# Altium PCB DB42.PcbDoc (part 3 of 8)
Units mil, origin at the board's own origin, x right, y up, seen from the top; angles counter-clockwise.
Board outline 3236.22 x 4456.69 mil, 8 copper layers (Top Layer, MidLayer1, MidLayer2, GND-Layer5, MidLayer3, VCC, MidLayer4, Bottom Layer), stack 62.194 mil thick; 214 components, 470 nets, 1802 pads, 1663 vias.
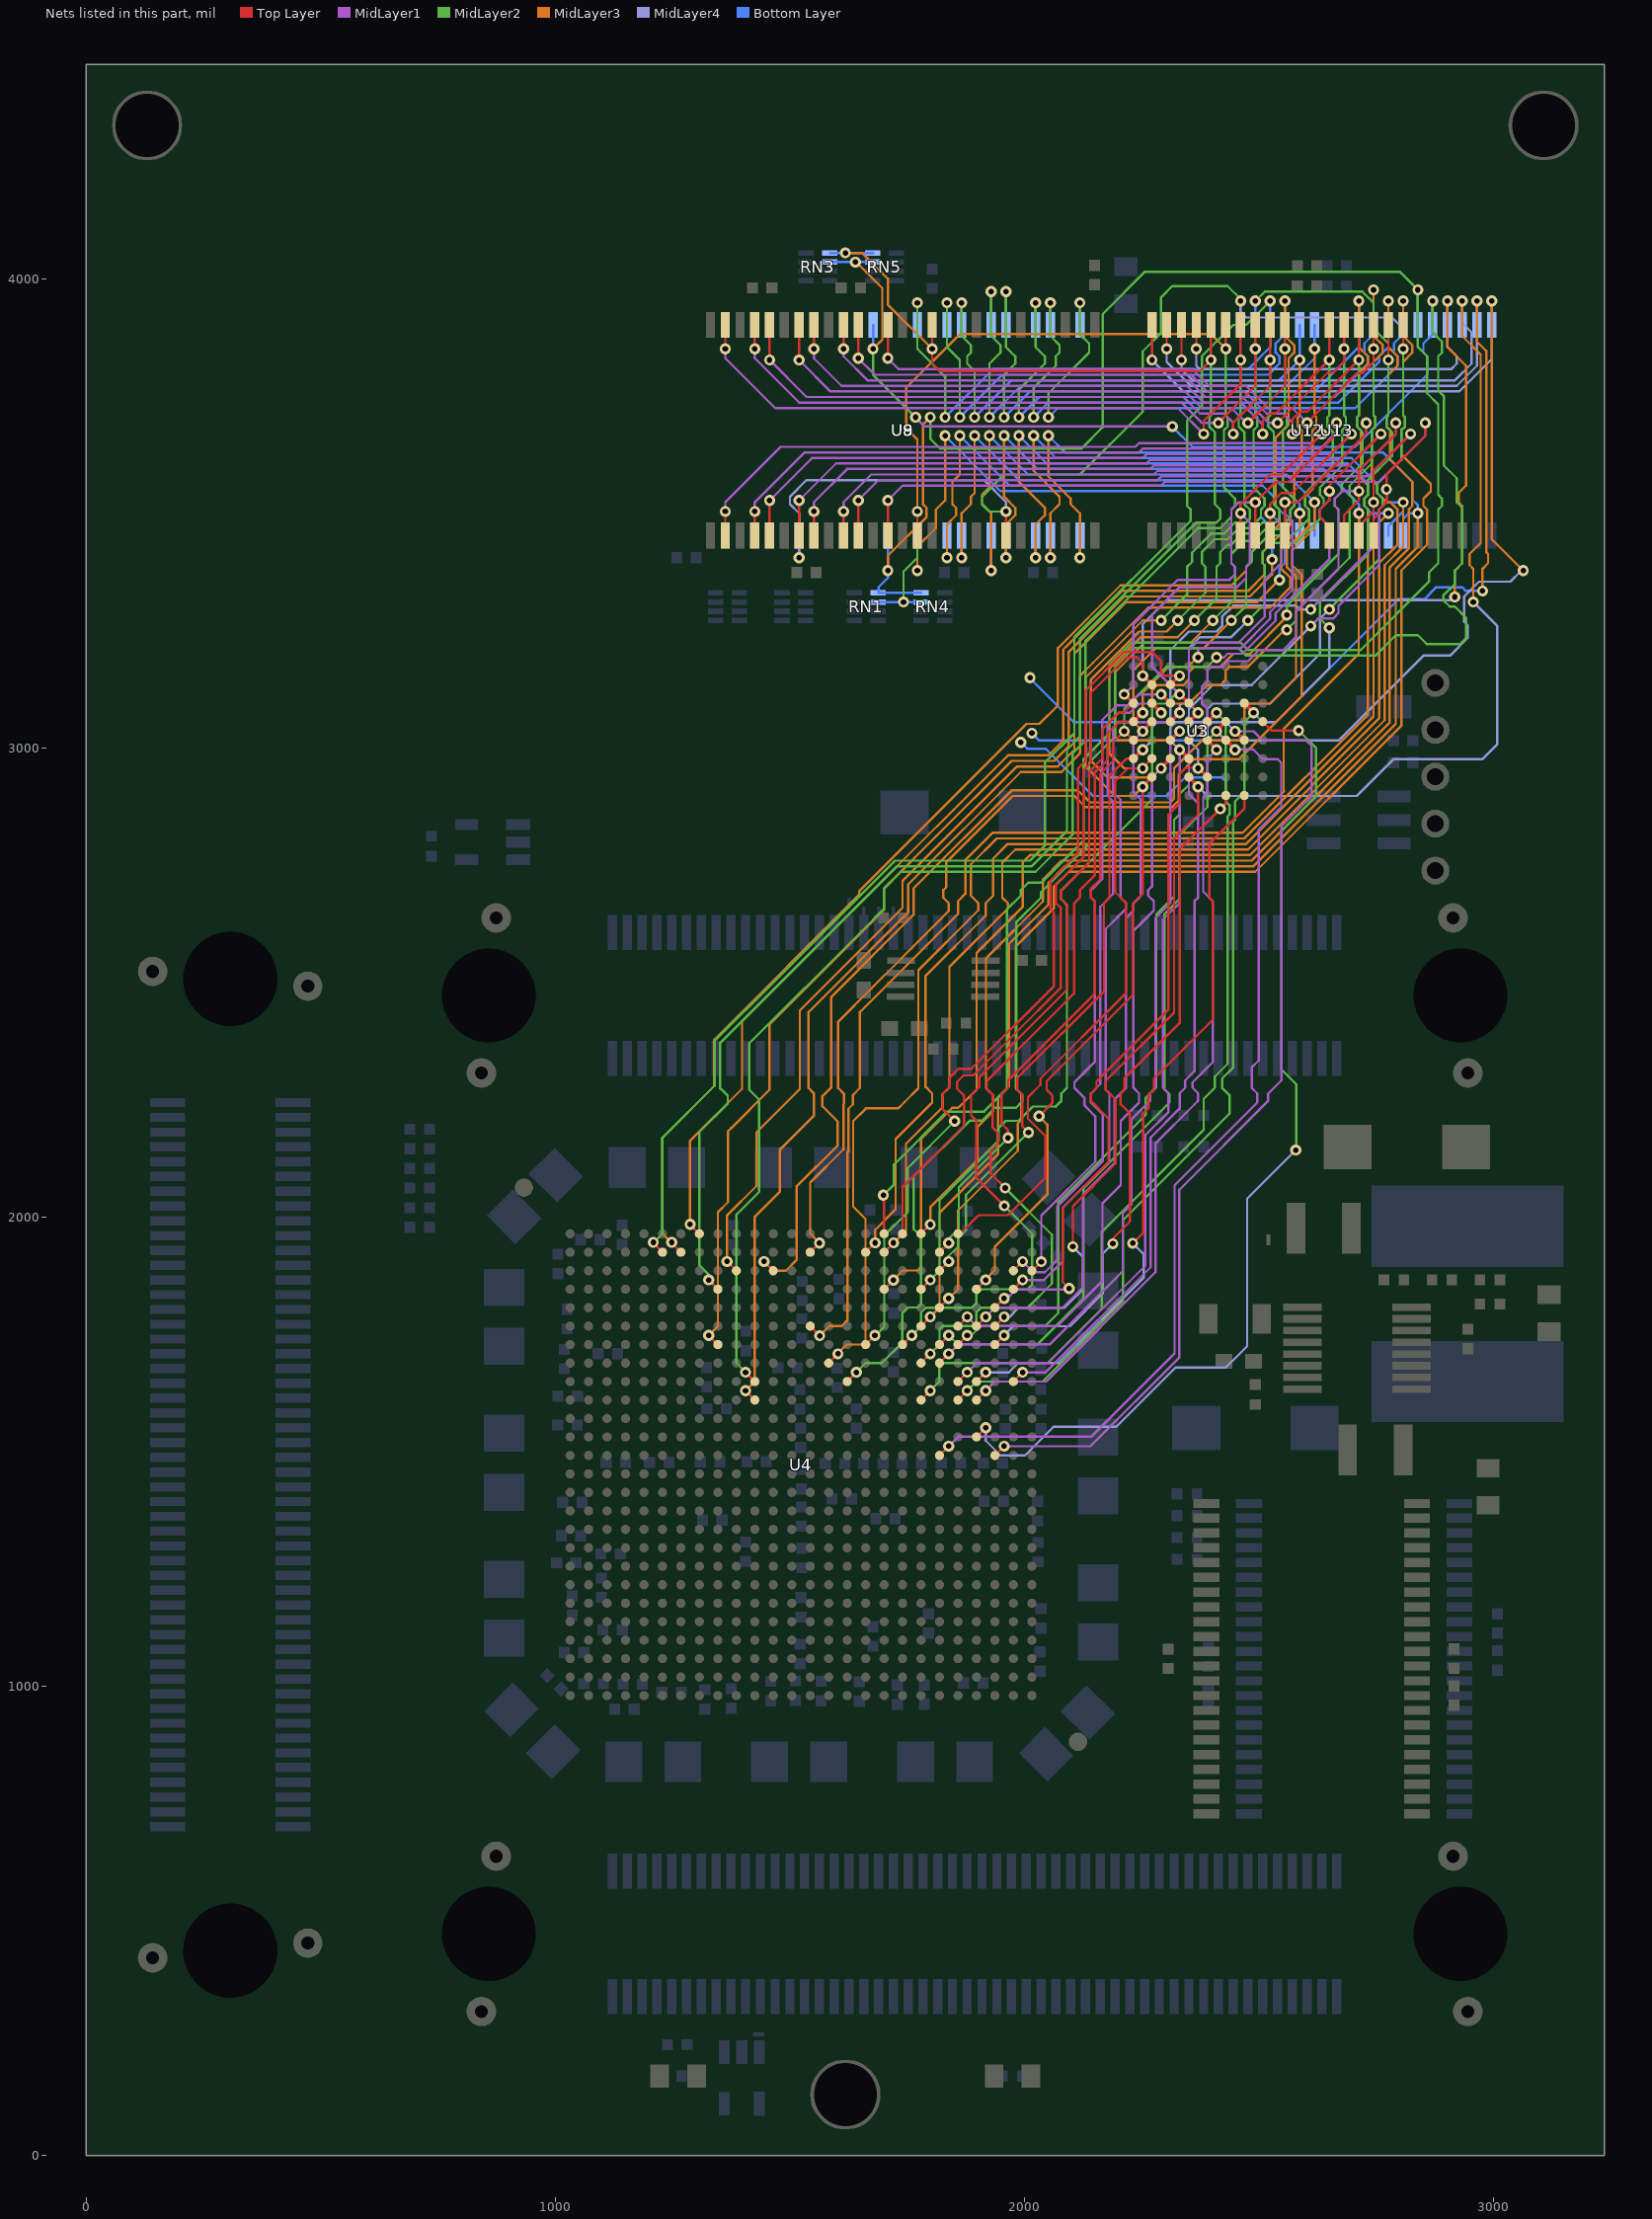
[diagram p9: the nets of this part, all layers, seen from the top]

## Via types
v1: diameter 23.62, hole 11.81, Top Layer to Bottom Layer, 1081 vias
v2: diameter 23.62, hole 11.81, Top Layer to Bottom Layer, tented both sides, 466 vias
v3: diameter 27.56, hole 15.75, Top Layer to Bottom Layer, 116 vias

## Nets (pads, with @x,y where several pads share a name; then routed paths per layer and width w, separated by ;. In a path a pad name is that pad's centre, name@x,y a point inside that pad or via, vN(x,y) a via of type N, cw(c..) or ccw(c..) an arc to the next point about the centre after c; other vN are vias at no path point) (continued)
BUS_A16: U3.D7 U4.E24 U8.21 U9.21 U12.27 U13.27 | length 4892.7
  Top Layer w5: U4.E24@1937.01,1807.09 v1(1956.69,1826.77) ; U8.21@1960.63,3452.76 v2(1960.63,3503.93) ; v1(2095,1848) 2081.5,1861.5 2081.5,2019.5 2179,2117.01 2179,2209.77 2141.73,2247.03 2141.73,2263.78 2153.54,2275.59 2153.54,2289.37 2307.09,2442.91 2307.09,2858.27 2330.71,2881.89 2330.71,2944.88 2343.51,2957.68 v1@2370.08,2957.68 ; v2(2807.09,3850.39) U12.27@2807.09,3901.57
  Top Layer w7.87: v1@2370.57,2957.19 U3.D7@2389.76,2937.99
  MidLayer1 w5: v1(1956.69,1826.77) 1963.11,1833.19 1969.97,1833.19 1982.86,1846.08 2092.88,1846.08 v1@2092.98,1845.98
  MidLayer2 w5: v2(1960.63,3503.93) 1925.2,3503.93 1909.45,3519.68 1909.45,3535.43 1925.2,3551.18 1956.69,3582.68 2118.11,3582.68 2251.97,3716.54 2251.97,3845.28 2291.34,3884.64 2291.34,3960.63 2314.96,3984.25 2433.07,3984.25 2460.63,3956.69 v2(2460.63,3952.76) ; v1(2649.61,3295.28) 2755.91,3401.57 2755.91,3507.87 2763.78,3515.75 2763.78,3531.5 2751.97,3543.31 2751.97,3562.99 2803.15,3614.17 2803.15,3677.17 2811.02,3685.04 2811.02,3704.72 2807.09,3708.66 v2(2807.09,3850.39)
  MidLayer4 w5: v2(1519.68,3405.51) 1519.68,3500 1500,3519.68 1500,3535.43 1535.43,3570.87 1913.38,3570.87 1960.63,3523.63 v2(1960.63,3503.93) ; v1(2370.08,2956.69) 2370.08,2996.06 2350.39,3015.75 2350.39,3043.31 2362.2,3055.12 2377.95,3055.12 2389.76,3066.93 2389.76,3082.68 2401.57,3094.49 2523.62,3094.49 2629.92,3200.79 2629.92,3275.59 v1(2649.61,3295.28) ; v2(2460.63,3952.76) 2460.63,3929.13 2472.44,3917.32 2783.46,3917.32 2807.09,3893.7 v2(2807.09,3850.39)
  Bottom Layer w5: v2(1519.68,3405.51) U9.21@1519.69,3452.76 ; U13.27@2460.63,3901.57 v2(2460.63,3952.76)
BUS_A17: U3.E7 U4.F24 U12.42 U13.42 | length 4073.9
  Top Layer w5: U4.F24@1937.01,1767.72 v1(1956.69,1787.4) ; v1(2103.15,1937.01) 2103.15,2023.32 2194,2114.17 2194,2250.88 2179.92,2264.97 2172.82,2272.06 2172.82,2289.76 2318.9,2435.84 2318.9,2807.09 2370.08,2858.27 v1(2370.08,2917.32) ; v2(2334.64,3826.77) U12.42@2334.64,3901.57
  Top Layer w7.87: U3.E7@2350.39,2937.99 v1(2370.08,2917.32)
  MidLayer3 w5: v2(2933.07,3952.76) 2933.07,3877.95 2972.44,3838.58 2972.44,3437.01 2948.82,3413.39 2948.82,3389.76 2956.69,3381.89 v1(2956.69,3311.02)
  MidLayer4 w5: v1(1956.69,1787.4) 1968.5,1787.4 1987.98,1806.88 2085.23,1806.88 2124.41,1846.06 2124.41,1915.75 v1(2103.15,1937.01) ; v2(2334.64,3826.77) 2334.64,3807.09 2358.27,3783.46 2917.32,3783.46 2952.76,3818.9 2952.76,3885.83 2933.07,3905.51 v2(2933.07,3952.76) ; v1(2370.08,2917.32) 2389.76,2897.64 2708.27,2897.64 2787.01,2976.38 2976.38,2976.38 3007.87,3007.87 3007.87,3259.84 v1(2956.69,3311.02)
  Bottom Layer w5: U13.42@2933.07,3901.57 v2(2933.07,3952.76)
BUS_A18: U3.B3 U4.K22 U12.43 U13.43 | length 4068.5
  Top Layer w5: U4.K22@1858.27,1610.24 v1(1877.95,1629.92) ; v2(2303.15,3850.39) U12.43@2303.15,3901.57
  Top Layer w7.87: U3.B3@2468.5,3095.47 v1@2488.19,3075.79
  MidLayer2 w5: v1(1877.95,1629.92) 1897.64,1649.61 2038.29,1649.61 2210.06,1821.38 2210.06,1993.58 2437.01,2220.53 2437.01,2259.84 2421.26,2275.59 2421.26,2295.28 2444.88,2318.9 2444.88,2673.23 2444.88,2842.52 2448.82,2846.46 2448.82,2885.83 2468.5,2905.51 2468.5,2976.38 2468.5,3055.12 v1(2488.19,3074.8)
  MidLayer3 w5: v2(2964.57,3952.76) 2964.57,3866.14 2984.25,3846.46 2984.25,3417.32 2988.19,3413.39 2988.19,3393.7 2976.38,3381.89 v1(2976.38,3334.65)
  MidLayer4 w5: v2(2303.15,3850.39) 2303.15,3822.83 2354.33,3771.65 2921.26,3771.65 2964.57,3814.96 v2(2964.57,3952.76)
  Bottom Layer w5: v1(2488.19,3074.8) 2507.87,3055.12 2535.43,3055.12 2796.99,3316.68 2852.11,3316.68 2877.95,3342.52 2933.07,3342.52 2940.94,3334.65 v1(2976.38,3334.65) ; U13.43@2964.57,3901.57 v2(2964.57,3952.76)
BUS_A19: U3.C4 U4.G21 U12.44 U13.44 | length 4235
  Top Layer w5: U4.G21@1818.9,1728.35 v1(1838.58,1748.03) ; v2(2271.65,3826.77) U12.44@2271.65,3901.57
  Top Layer w7.87: v1(2409.45,3035.43) U3.C4@2429.13,3056.1
  MidLayer2 w5: v1(1838.58,1748.03) 1858.27,1728.35 2027.48,1728.35 2125.44,1826.3 2125.44,2060.5 2309.45,2244.5 2309.45,2261.23 2298.62,2272.06 2298.62,2645.98 2330.71,2678.06 2330.71,2814.96 2389.76,2874.02 2389.76,3015.75 v1(2409.45,3035.43)
  MidLayer3 w5: v2(2996.06,3952.76) 2996.06,3633.86 2996.06,3444.88 v1(3062.99,3377.95)
  MidLayer4 w5: v2(2271.65,3826.77) 2338.58,3759.84 2926.67,3759.84 2996.06,3829.23 v2(2996.06,3952.76) ; v1(2409.45,3035.43) 2429.13,3015.75 2669.29,3015.75 2850.39,3196.85 2906.85,3196.85 2944.88,3234.88 2944.88,3260.83 2937.01,3268.7 2937.01,3322.83 2968.5,3354.33 3035.43,3354.33 3059.06,3377.95 v1(3062.99,3377.95)
  Bottom Layer w5: U13.44@2996.06,3901.57 v2(2996.06,3952.76)
BUS_A20: U3.D5 U4.K23 U12.28 U13.28 | length 3357.9
  Top Layer w5: U4.K23@1897.64,1610.24 v1(1917.32,1629.92) ; v2(2775.59,3826.77) U12.28@2775.59,3901.57
  Top Layer w7.87: U3.D5@2389.76,3016.73 v1(2409.45,2996.06)
  MidLayer1 w5: v1(1917.32,1629.92) 1937.01,1649.61 2046.16,1649.61 2279.03,1882.48 2279.03,2156.98 2362.44,2240.4 2370.08,2248.03 2370.08,2263.78 2358.27,2275.59 2358.27,2287.4 2401.57,2330.71 2401.57,2673.23 2380.91,2693.9 2380.91,2894.69 2389.76,2903.54 2389.76,2976.38 v1(2409.45,2996.06)
  MidLayer2 w5: v2(2492.13,3952.76) 2511.81,3972.44 2720.47,3972.44 2744.09,3948.82 2744.09,3893.7 2775.59,3862.21 v2(2775.59,3826.77) 2775.59,3708.66 2771.65,3704.72 2771.65,3685.04 2783.46,3673.23 2783.46,3622.05 2732.28,3570.87 2732.28,3539.37 2724.41,3531.5 2724.41,3515.75 2732.28,3507.87 2732.28,3413.39 2629.92,3311.02 2629.92,3275.59 v1(2649.61,3255.91)
  MidLayer4 w5: v1(2409.45,2996.06) 2389.76,3015.75 2389.76,3043.31 2401.57,3055.12 2535.43,3055.12 2649.61,3169.29 v1(2649.61,3255.91)
  Bottom Layer w5: U13.28@2492.13,3901.57 v2(2492.13,3952.76)
BUS_A21: U3.D4 U4.K20 | length 1904.6
  Top Layer w5: U4.K20@1779.53,1610.24 v1(1799.21,1629.92)
  Top Layer w7.87: U3.D4@2389.76,3056.1 v1(2409.45,3074.8)
  MidLayer2 w5: v1(1799.21,1629.92) 1818.52,1649.23 1818.52,1678.76 1828.74,1688.98 2049.21,1688.98 2164.65,1804.41 2164.65,1968.7 2381.89,2185.95 2381.89,2251.97 2405.51,2275.59 2405.51,2299.21 2433.07,2326.77 2433.07,2749.01 2433.07,2854.33 2437.01,2858.27 2437.01,2877.95 2429.13,2885.83 2429.13,2909.45 2429.13,3055.12 v1(2409.45,3074.8)
BUS_A22: U3.C5 U4.N21 | length 2538.3
  Top Layer w5: U4.N21@1818.9,1492.13 v1(1838.58,1511.81)
  Top Layer w7.87: U3.C5@2429.13,3016.73 v1@2448.82,2997.05
  MidLayer1 w5: v1(1838.58,1511.81) 1858.64,1531.87 2142.08,1531.87 2319.88,1709.67 2319.88,2067.91 2496.06,2244.09 2496.06,2263.78 2484.25,2275.59 2484.25,2318.9 2499.36,2334.01 2499.36,2826.05 2547.24,2873.93 2547.24,2968.5 2539.37,2976.38 2507.87,2976.38 2487.2,2997.05 v1@2448.82,2997.05
  Bottom Layer w5: v1(2015.75,3031.5) 2031.5,3015.75 2429.13,3015.75 v1@2447.83,2997.05
  other v1: 2448.82,2996.06
BUS_A23: U3.B8 U4.J23 | length 1604.7
  Top Layer w5: U4.J23@1897.64,1649.61 v1(1917.32,1669.29) ; v1(2230.73,1944.38) 2253.36,1967.02 2253.36,2221.36 2255,2223 ; 2254.75,2223.25 2264.96,2233.46 2264.96,2261.02 2275.59,2271.65 2275.59,2295.27 2401.57,2421.26 2401.57,2673.23 2393.7,2681.1 2393.7,2731.56 ; 2393.7,2716.54 2393.7,2795.28 2468.51,2870.08 U3.B8@2468.5,2898.62
  MidLayer4 w5: v1@1918.3,1669.29 1966.93,1669.29 1986.72,1689.08 2072.15,1689.08 2254.44,1871.37 2254.44,1920.67 v1(2230.73,1944.38)
BUS_A24: U3.C8 U4.G24 | length 2027.6
  Top Layer w5: U4.G24@1937.01,1728.35 v1(1956.69,1748.03) ; v1@2189.4,1944.38 2189.4,1955.21 2224.82,1990.63 2224.82,2220.74 2205,2240.57 2205,2264.05 2212.8,2271.85 2212.8,2295.47 2330.71,2413.39 2330.71,2783.46 2429.14,2881.89 U3.C8@2429.13,2898.62
  MidLayer4 w5: v1(1956.69,1748.03) 1956.69,1748.27 1975.91,1767.48 2096.62,1767.48 2166.54,1837.4 2166.54,1921.52 v1(2188.42,1943.4)
  Bottom Layer w5: v1(1992.13,3011.81) 2006.09,2998.31 2045.43,2998.31 2146.1,2897.64 2303.15,2897.64 2342.52,2937.01 2421.26,2937.01 2429.13,2929.13 2429.13,2881.89 v1(2417.32,2870.08)
BUS_D0: U3.E3 U4.D20 U8.2 U12.7 | length 3891.2
  Top Layer w5: U8.2@1362.21,3452.76 v2(1362.2,3503.93) ; U4.D20@1779.53,1846.46 v1(1799.21,1866.14) ; U12.7@2460.63,3452.76 v1(2460.63,3500) 2460.63,3519.69 2523.62,3582.68 2547.24,3582.68 v2(2633.86,3669.29)
  Top Layer w7.87: v1(2330.71,3114.17) U3.E3@2350.4,3095.48
  MidLayer1 w5: v2(1362.2,3503.93) 1362.2,3523.62 1480.31,3641.73 2236.22,3641.73 2244.09,3649.61 2614.17,3649.61 v2(2633.86,3669.29) ; v1(2330.71,3114.17) 2271.65,3173.23 2271.65,3283.46 2330.71,3342.52 2452.76,3342.52 2472.44,3362.2 2472.44,3385.83 2480.31,3393.7 2480.31,3480.32 v1(2460.63,3500)
  MidLayer2 w5: v1(1799.21,1866.14) 1818.9,1885.83 1818.9,2036.73 1944.38,2162.21 1944.38,2189.4 1960.13,2205.14 1987.68,2205.14 2018.18,2235.65 2066.4,2235.65 ; 2066.57,2235.47 2077.1,2246 2078.74,2247.64 2078.74,2263.78 2090.55,2275.59 2090.55,2665.35 2078.74,2677.17 2078.74,2696.85 2094.49,2712.6 ; 2084.64,2702.76 2271.65,2889.77 2271.65,3086.61 2279.53,3094.49 2302.17,3094.49 2321.85,3114.17 v1(2330.71,3114.17)
BUS_D1: U3.H3 U4.G19 U8.4 U12.8 | length 4174.9
  Top Layer w5: U8.4@1425.2,3452.76 v2(1425.19,3503.93) ; U4.G19@1740.16,1728.35 v1(1759.84,1748.03) ; v1(1957,2024) 1897,2084 1897,2206 1886.22,2216.78 1886.22,2260.24 1903.54,2277.56 1903.54,2297.64 2090.94,2485.04 2090.94,2664.96 2078.74,2677.17 2078.74,2696.85 2137.8,2755.91 2137.8,2949.54 2165.35,2977.1 2165.35,3039.37 2201.28,3075.3 2212.1,3075.3 U3.H3@2232.29,3095.48 ; U12.8@2492.13,3452.76 v1(2492.13,3523.62) 2535.43,3566.93 2562.99,3566.93 2665.35,3669.29 v2(2665.35,3692.91)
  Top Layer w7.87: v1(2212.6,3114.17) U3.H3@2232.29,3095.48
  MidLayer1 w5: v2(1425.19,3503.93) 1425.19,3523.62 1531.5,3629.92 2244.09,3629.92 2251.97,3637.8 2629.92,3637.8 2665.35,3673.23 v2(2665.35,3692.91) ; v1(2212.6,3114.17) 2232.28,3133.86 2232.28,3263.78 2326.77,3358.27 2437.01,3358.27 2448.82,3370.08 2448.82,3385.83 2440.94,3393.7 2440.94,3507.87 2456.69,3523.62 v1(2492.13,3523.62)
  MidLayer2 w5: v1(1759.84,1748.03) 1779.53,1767.72 1779.53,1796.46 1790.16,1807.09 1887.8,1807.09 1897.64,1816.93 1897.64,1835.83 1908.27,1846.46 2006.69,1846.46 2016.14,1855.91 2016.14,1964.86 v1(1957,2024)
BUS_D2: U3.E4 U4.G22 U8.5 U12.9 | length 3924.7
  Top Layer w5: U8.5@1456.69,3452.76 v2(1456.69,3527.55) ; U4.G22@1858.27,1728.35 v1(1877.95,1748.03) ; U12.9@2523.62,3452.76 v1(2523.62,3500) 2523.62,3519.69 2547.24,3543.31 2570.87,3543.31 v2(2696.85,3669.29)
  Top Layer w7.87: U3.E4@2350.39,3056.1 v1(2370.08,3074.81)
  MidLayer1 w5: v2(1456.69,3527.55) 1547.24,3618.11 2251.97,3618.11 2259.84,3625.98 2653.54,3625.98 v2(2696.85,3669.29) ; v1(2370.08,3074.81) 2350.39,3094.5 2350.39,3208.66 2366.14,3224.41 2456.69,3224.41 2511.81,3279.53 2511.81,3358.27 2547.24,3393.7 2547.24,3476.38 v1(2523.62,3500)
  MidLayer2 w5: v1(1877.95,1748.03) 1887.01,1748.03 1906.69,1767.71 2043.77,1767.71 2072.3,1796.25 2072.3,2031.96 2258.28,2217.94 2258.28,2254.34 2280.91,2276.98 2280.91,2645.38 2318.9,2683.37 2318.9,2846.46 2330.71,2858.27 2330.71,2901.57 2350.39,2921.26 2350.39,3055.12 v1(2370.08,3074.81)
BUS_D3: U3.H4 U4.H20 U8.7 U12.10 | length 4178.9
  Top Layer w5: U8.7@1519.69,3452.76 v2(1519.68,3527.56) ; U4.H20@1779.53,1688.98 v1(1799.21,1708.66) ; v1(1959,2062) 1928,2093 1928,2141 1943.4,2156.4 1943.4,2179.56 1932.32,2190.64 1932.32,2260.59 1920.08,2272.83 1920.08,2290.55 1970.67,2341.14 ; 1970.47,2341.34 2087.88,2458.75 2105.53,2476.39 2105.53,2668.52 2118.11,2681.1 2118.11,2696.85 2149.61,2728.35 2149.61,2947.21 2177.17,2974.77 2177.17,3031.5 2201.78,3056.11 U3.H4@2232.28,3056.1 ; U12.10@2555.12,3452.76 v1(2555.12,3523.62) 2582.68,3523.62 2640.75,3581.69 2728.35,3669.29 v2(2728.35,3692.91)
  Top Layer w7.87: U3.H4@2232.28,3056.1 v1@2251.47,3075.3
  MidLayer1 w5: v2(1519.68,3527.56) 1598.43,3606.3 2259.84,3606.3 2267.72,3614.17 2673.23,3614.17 2728.35,3669.29 v2(2728.35,3692.91) ; v1(2370.08,3192.91) 2370.08,3208.66 2374.02,3212.6 2460.63,3212.6 2523.62,3275.59 2523.62,3289.73 2571,3337.11 2571,3484.12 2555.12,3500 v1(2555.12,3523.62)
  MidLayer2 w5: v1(1799.21,1708.66) 1799.21,1709.06 1818.9,1728.74 1818.9,1761.02 1825.59,1767.72 1887.4,1767.72 1897.64,1777.95 1897.64,1797.24 1907.48,1807.09 2007.09,1807.09 2058.27,1858.27 2058.27,1962.73 v1(1959,2062)
  MidLayer3 w5: v1(2251.97,3074.8) 2251.97,3118.11 2255.91,3122.05 2307.09,3173.23 2348.06,3173.23 2367.75,3192.91 v1(2370.08,3192.91)
BUS_D4: U3.H5 U4.B21 U8.8 U12.13 | length 3724.4
  Top Layer w5: U8.8@1551.18,3452.76 v2(1551.18,3503.94) ; U4.B21@1818.9,1925.2 v1(1838.58,1944.88) ; v1(1965.05,2168.74) 1965.05,2185.46 1951.18,2199.33 1951.18,2262.2 1965.35,2276.38 1965.35,2291.31 2149.61,2475.56 2149.61,2673.23 2141.73,2681.1 2141.73,2700.79 2161.42,2720.47 2161.42,2944.88 2188.98,2972.44 2188.98,3011.81 v1(2212.6,3035.43) U3.H5@2232.28,3016.73 ; U12.13@2649.61,3452.76 2649.61,3472.44 2629.92,3492.13 2629.92,3507.87 2649.61,3527.56 v1(2649.61,3547.24) 2649.61,3559.06 v2(2759.84,3669.29)
  MidLayer1 w5: v2(1551.18,3503.94) 1551.18,3523.62 1622.05,3594.49 2267.72,3594.49 2275.59,3602.36 2692.91,3602.36 v2(2759.84,3669.29) ; v1(2409.45,3192.91) 2425.2,3192.91 2433.07,3200.79 2464.57,3200.79 2535.43,3271.65 2535.43,3287.4 2649.61,3401.57 2649.61,3472.44 2629.92,3492.13 2629.92,3507.87 2649.61,3527.56 v1(2649.61,3547.24)
  MidLayer2 w5: v1(1838.58,1944.88) 1838.58,1953.54 1860,1974.96 1860,2063.69 v1(1965.05,2168.74) ; v1(2212.6,3035.43) 2212.6,3082.68 2303.15,3173.23 2389.76,3173.23 v1(2409.45,3192.91)
BUS_D5: U3.E5 U4.J25 U8.10 U12.14 | length 4014.6
  Top Layer w5: U8.10@1614.17,3452.76 v2(1614.17,3503.93) ; U4.J25@1976.38,1649.61 v1(1996.06,1669.29) ; U12.14@2681.1,3452.76 2681.1,3496.06 2712.6,3527.56 v1(2712.6,3547.24) 2712.6,3590.55 2791.34,3669.29 v2(2791.34,3692.91)
  Top Layer w7.87: U3.E5@2350.39,3016.73 v1(2370.08,3035.43)
  MidLayer1 w5: v2(1614.17,3503.93) 1614.17,3523.62 1673.23,3582.68 2275.59,3582.68 2283.46,3590.55 2712.6,3590.55 2791.34,3669.29 v2(2791.34,3692.91) ; v1(1996.06,1669.29) 2045.18,1669.29 2268.98,1893.09 2268.98,2169.6 2330.71,2231.32 2330.71,2263.78 2342.52,2275.59 2342.52,2291.34 2362.2,2311.02 2362.2,2673.23 2370.08,2681.1 2370.08,2720.47 ; 2370.08,2704.72 2370.08,2720.47 ; v1(2712.6,3547.24) 2677.17,3547.24 2661.42,3531.5 2661.42,3515.75 2669.29,3507.87 2669.29,3381.89 2578.74,3291.34 2578.74,3236.22 2551.18,3208.66 2500,3208.66 2476.38,3185.04 2433.07,3185.04 2421.26,3173.23 2397.64,3173.23 2389.76,3165.35 2389.76,3141.73 2377.95,3129.92 2377.95,3094.49 2389.76,3082.68 2389.76,3055.12 v1(2370.08,3035.43) 2350.39,3015.75 2350.39,2901.57 2370.08,2881.89 2370.08,2720.47
BUS_D6: U3.H6 U4.C21 U8.11 U12.15 | length 3777.6
  Top Layer w5: U8.11@1645.67,3452.76 v2(1645.66,3527.55) ; U4.C21@1818.9,1885.83 v1(1838.58,1905.51) ; v1(2008.34,2180.54) 1995.28,2193.61 1995.28,2260.63 1984.41,2271.49 1984.41,2296.22 2169.29,2481.1 2169.29,2669.29 2181.1,2681.1 2181.1,2940.94 2217.52,2977.37 U3.H6@2232.28,2977.36 ; U12.15@2712.6,3452.76 2712.6,3472.44 2744.09,3503.94 v1(2744.09,3523.62) 2744.09,3590.55 v2(2822.83,3669.29)
  Top Layer w7.87: U3.H6@2232.28,2977.36 2251.47,2996.56 v1@2251.97,2997.05
  MidLayer1 w5: v2(1645.66,3527.55) 1688.98,3570.87 2283.46,3570.87 2291.34,3578.74 2732.28,3578.74 v2(2822.83,3669.29) ; v1(2610.24,3295.28) 2744.09,3429.13 v1(2744.09,3523.62)
  MidLayer2 w5: v1(1838.58,1905.51) 1838.58,1917.33 1858.27,1937.01 1858.27,1955.12 1865.55,1962.4 ; 1865.75,1962.21 1875.59,1972.05 1875.59,2047.79 v1(2008.34,2180.54)
  MidLayer4 w5: v1(2251.97,2996.06) 2271.65,3015.75 2271.65,3043.31 2283.46,3055.12 2303.15,3055.12 2311.02,3062.99 2311.02,3208.66 2350.39,3248.03 2409.45,3248.03 2421.26,3259.84 2421.26,3279.53 2444.88,3303.15 2578.74,3303.15 2586.61,3295.28 v1(2610.24,3295.28)
BUS_D7: U3.E6 U4.J22 U8.13 U12.16 | length 4110.9
  Top Layer w5: U8.13@1708.66,3452.76 v2(1708.66,3527.55) ; U4.J22@1858.27,1649.61 v1(1877.95,1669.29) ; U12.16@2744.09,3452.76 2744.09,3488.19 2755.91,3500 2755.91,3507.87 2771.65,3523.62 v1(2771.65,3551.18) 2771.65,3582.68 2854.33,3665.35 v2(2854.33,3692.91)
  Top Layer w7.87: v1@2330.71,2997.05 2331.2,2996.56 U3.E6@2350.39,2977.36
  MidLayer1 w5: v2(1708.66,3527.55) 1740.16,3559.06 2291.34,3559.06 2299.21,3566.93 2755.91,3566.93 2854.33,3665.35 v2(2854.33,3692.91) ; v1(1877.95,1669.29) 1897.64,1688.98 2050.1,1688.98 2257.3,1896.17 2257.3,2174.64 2307.09,2224.43 2307.09,2263.78 2295.28,2275.59 2295.27,2633.86 2330.71,2669.29 2330.71,2700.79 ; 2330.71,2681.1 v1(2330.71,2996.06) v1@2330.71,2997.05 ; v1(2610.24,3259.84) 2625.98,3275.59 2657.48,3275.59 2669.29,3287.4 2669.29,3303.15 2755.91,3389.76 2755.91,3507.87 2771.65,3523.62 v1(2771.65,3551.18)
  MidLayer4 w5: v1(2330.71,2996.06) 2311.02,3015.75 2311.02,3043.31 2322.83,3055.12 2338.58,3055.12 2350.39,3066.93 2350.39,3082.68 2401.57,3133.86 2484.25,3133.86 v1(2610.24,3259.84)
BUS_D8: U3.F3 U4.C26 U8.42 U12.29 | length 3791.8
  Top Layer w5: v2(1708.66,3830.71) U8.42@1708.66,3901.57 ; U4.C26@2016.14,1886.22 U4.C26@2016.14,1886.61 ; U4.C26@2016.14,1887.8 U4.C26@2016.14,1886.61 ; v1(2035.83,1905.12) 2017.32,1886.61 U4.C26@2016.14,1886.61 ; v2(2602.36,3692.91) 2708.17,3798.72 2719.98,3798.72 2744.09,3822.83 v2(2744.09,3850.39) U12.29@2744.09,3901.57
  Top Layer w7.87: v1@2291.34,3115.16 2291.83,3114.67 U3.F3@2311.03,3095.48
  MidLayer1 w5: v2(1708.66,3830.71) 1732.28,3807.09 2358.27,3807.09 2393.7,3771.65 2472.44,3771.65 2519.69,3724.41 2570.87,3724.41 v2(2602.36,3692.91) ; v1@2037,1906.29 v1(2035.83,1905.12) 2035.83,2003.23 2151,2118.4 2151,2215 2136,2230 ; 2136.07,2230.07 2127.45,2238.69 2127.45,2254.44 2106.3,2275.59 2106.3,2287.4 2149.61,2330.71 2149.61,2645.67 2149.61,2673.23 2141.73,2681.1 2141.73,2696.85 2165.35,2720.47 2165.35,3059.06 2196.85,3090.55 2220.47,3090.55 2244.09,3114.17 v1(2291.34,3114.17)
  MidLayer2 w5: v1(2559.06,3251.97) 2578.74,3271.65 2578.74,3291.34 2692.91,3405.51 2692.91,3507.87 2700.79,3515.75 2700.79,3531.5 2692.91,3539.37 2692.91,3559.06 2740.16,3606.3 2740.16,3677.17 2748.03,3685.04 2748.03,3704.72 2744.09,3708.66 v2(2744.09,3850.39)
  MidLayer3 w5: v1(2291.34,3114.17) 2311.02,3094.49 2350.39,3094.49 2389.76,3133.86 2417.32,3133.86 2429.13,3145.67 2429.13,3165.35 2437.01,3173.23 2476.38,3173.23 2555.12,3251.97 v1(2559.06,3251.97)
BUS_D9: U3.G3 U4.C25 U8.44 U12.30 | length 3953.2
  Top Layer w5: v2(1645.67,3830.71) U8.44@1645.67,3901.57 ; U4.C25@1976.38,1885.83 v1(1996.06,1905.51) ; v2(2570.87,3669.29) 2570.87,3700.79 2586.61,3716.54 2602.36,3716.54 v2(2712.6,3826.77) U12.30@2712.6,3901.57
  Top Layer w7.87: U3.G3@2271.65,3095.48 v1(2291.34,3074.8)
  MidLayer1 w5: v2(1645.67,3830.71) 1681.1,3795.28 2354.33,3795.28 2389.76,3759.84 2469,3759.84 2516.24,3712.6 2551.18,3712.6 2570.87,3692.91 v2(2570.87,3669.29) ; v1(1996.06,1905.51) 2018.9,1882.68 2043.68,1882.68 2069.35,1908.35 2069.35,2021.99 2167,2119.64 2167,2218.83 2141.73,2244.09 2141.73,2263.78 2161.42,2283.46 2161.42,2661.42 2188.98,2688.98 2188.98,2724.41 ; 2188.98,2700.79 2188.98,2885.83 2177.17,2897.64 2177.17,3051.18 2200.79,3074.8 2224.41,3074.8 2244.09,3094.49 2271.65,3094.49 v1(2291.34,3074.8)
  MidLayer2 w5: v1(2559.06,3283.46) 2559.06,3303.15 2669.29,3413.39 2669.29,3507.87 2661.42,3515.75 2661.42,3531.5 2676.18,3546.26 2676.18,3562.01 2720.47,3606.3 2720.47,3673.23 2708.66,3685.04 2708.66,3704.72 2712.6,3708.66 v2(2712.6,3826.77)
  MidLayer3 w5: v1(2291.34,3074.8) 2271.65,3094.49 2271.65,3122.05 2283.46,3133.86 2338.58,3133.86 2350.39,3145.67 2350.39,3161.42 2362.2,3173.23 2417.32,3173.23 2444.88,3200.79 2480.31,3200.79 2559.06,3279.53 v1(2559.06,3283.46)
BUS_D10: U3.F4 U4.D25 U8.45 U12.31 | length 3864.5
  Top Layer w5: v2(1614.17,3850.39) U8.45@1614.17,3901.57 ; U4.D25@1976.38,1846.46 v1(1996.06,1866.14) ; v2@2537.4,3694.88 2539.37,3694.88 2541.34,3694.88 2646.65,3800.2 2658.46,3800.2 2681.1,3822.83 v2(2681.1,3850.39) U12.31@2681.1,3901.57
  Top Layer w7.87: U3.F4@2311.02,3056.1 v1(2330.71,3074.8)
  MidLayer1 w5: v2(1614.17,3850.39) 1614.17,3834.65 1665.35,3783.46 2350.39,3783.46 2385.83,3748.03 2464.57,3748.03 2519.69,3692.91 v2(2539.37,3692.91) ; v1(1996.06,1866.14) 2041.73,1866.14 2082.14,1906.55 2082.14,2020.33 2180.87,2119.06 2180.87,2264.02 2173.23,2271.66 2173.23,2614.17 2216.53,2657.48 2216.53,2669.29 2204.72,2681.1 2204.72,2708.66 ; 2204.72,2700.79 2204.72,2889.76 2188.98,2905.51 2188.98,3043.31 2200.79,3055.12 2311.02,3055.12 v1(2330.71,3074.8)
  MidLayer2 w5: v1(2476.38,3271.65) 2511.81,3307.09 2511.81,3389.76 2507.87,3393.7 2507.87,3417.32 2527.56,3437.01 2578.74,3437.01 2629.92,3488.19 2629.92,3507.87 2637.8,3515.75 2637.8,3531.5 2629.92,3539.37 2629.92,3555.12 2677.16,3602.36 2677.16,3677.17 2685.04,3685.04 2685.04,3704.72 2681.1,3708.66 v2(2681.1,3850.39)
  MidLayer4 w5: v1(2330.71,3074.8) 2330.71,3090.55 2334.65,3094.49 2342.52,3094.49 2350.39,3102.36 2350.39,3212.6 2374.02,3236.22 2440.94,3236.22 v1(2476.38,3271.65)
BUS_D11: U3.G4 U4.F23 U8.47 U12.32 | length 4023.3
  Top Layer w5: v2(1551.18,3850.39) U8.47@1551.18,3901.57 ; U4.F23@1897.64,1767.72 v1(1917.32,1787.4) ; v2(2507.87,3669.29) 2507.87,3696.85 2523.62,3712.6 2535.43,3712.6 v2(2649.61,3826.77) U12.32@2649.61,3901.57
  Top Layer w7.87: v1(2251.97,3035.43) U3.G4@2271.65,3056.1
  MidLayer1 w5: v2(1551.18,3850.39) 1551.18,3830.71 1610.24,3771.65 2346.46,3771.65 2381.89,3736.22 2460.63,3736.22 2507.87,3688.98 v2(2507.87,3669.29) ; v1(1917.32,1787.4) 1936.63,1806.71 2081.25,1806.71 2124.46,1849.92 2124.46,2047.58 2192.35,2115.47 2192.35,2251.41 2216.53,2275.59 2216.54,2637.8 2232.28,2653.54 2232.28,2669.29 2248.03,2685.04 2248.03,2889.76 2232.28,2905.51 2232.28,3015.75 v1(2251.97,3035.43)
  MidLayer2 w5: v1(2440.94,3271.65) 2472.44,3303.15 2472.44,3385.83 2484.25,3397.64 2484.25,3417.32 2519.69,3452.76 2570.87,3452.76 2606.3,3488.19 2606.3,3507.87 2598.43,3515.75 2598.43,3543.31 2657.48,3602.36 2657.48,3673.23 2645.67,3685.04 2645.67,3704.72 2649.61,3708.66 v2(2649.61,3826.77)
  MidLayer3 w5: v1(2251.97,3035.43) 2232.28,3055.12 2232.28,3165.35 2279.53,3212.6 2381.89,3212.6 v1(2440.94,3271.65)
BUS_D12: U3.F5 U4.H21 U8.48 U12.35 | length 4274.2
  Top Layer w5: v2(1519.68,3826.77) U8.48@1519.69,3901.57 ; U4.H21@1818.9,1688.98 v1(1838.58,1708.66) ; v2(2476.38,3692.91) 2555.12,3771.65 v2(2555.12,3850.39) U12.35@2555.12,3901.57
  Top Layer w7.87: U3.F5@2311.02,3016.73 v1(2330.71,3035.43)
  MidLayer1 w5: v2(1519.68,3826.77) 1586.6,3759.84 2342.52,3759.84 2377.95,3724.41 2440.94,3724.41 2472.44,3692.91 v2(2476.38,3692.91) ; v1(1838.58,1708.66) 1858.64,1728.72 2053.44,1728.72 2209.41,1884.69 2209.41,2008.67 2227.56,2026.82 2227.56,2207.87 2267.72,2248.03 2267.72,2263.78 2279.53,2275.59 2279.53,2637.79 2311.02,2669.29 2311.02,3015.75 v1(2330.71,3035.43) 2330.22,3035.93 v1@2326.78,3039.37
  MidLayer2 w5: v1(2401.57,3271.65) 2448.82,3318.9 2448.82,3385.83 2440.94,3393.7 2440.94,3413.39 2468.5,3440.94 2488.19,3440.94 2513.78,3466.54 2541.34,3466.54 2547.24,3472.44 2566.93,3492.13 2566.93,3507.87 2574.8,3515.75 2574.8,3531.5 2555.12,3551.18 2551.18,3555.12 2551.18,3677.17 2559.05,3685.04 2559.05,3704.72 2555.12,3708.66 v2(2555.12,3850.39)
  MidLayer3 w5: v1(2330.71,3035.43) 2311.02,3015.75 2200.79,3015.75 2192.91,3023.62 2192.91,3161.42 2255.91,3224.41 2354.33,3224.41 v1(2401.57,3271.65)
BUS_D13: U3.G6 U4.A22 U8.50 U12.36 | length 3876.4
  Top Layer w5: v2(1456.69,3826.77) U8.50@1456.69,3901.57 ; U4.A22@1858.27,1964.57 1862.6,1964.57 1902.16,2004.13 1964.89,2004.13 2044.75,2083.98 2044.75,2172.67 2007.36,2210.06 2007.36,2255.64 2034.25,2282.53 2034.25,2295.28 2208.38,2469.4 2216.54,2477.56 2216.54,2669.29 2192.91,2692.91 2192.91,2838.58 ; 2192.91,2822.83 2192.91,2929.14 2220.47,2956.69 v1(2251.97,2956.69) ; v1@2251.97,2957.68 U3.G6@2271.65,2977.36 ; v2(2444.88,3669.29) 2444.88,3692.91 2523.62,3771.65 v2(2523.62,3826.77) U12.36@2523.62,3901.57
  MidLayer1 w5: v2(1456.69,3826.77) 1535.43,3748.03 2338.58,3748.03 2374.02,3712.6 2425.2,3712.6 2444.88,3692.91 v2(2444.88,3669.29)
  MidLayer2 w5: v1(2362.2,3271.65) 2409.45,3318.9 2409.45,3385.83 2417.32,3393.7 2417.32,3417.32 2433.07,3433.07 2440.94,3433.07 2464.57,3456.69 2484.25,3456.69 2507.87,3480.32 2523.62,3480.32 2535.43,3480.31 2543.31,3488.19 2543.31,3507.87 2531.5,3519.69 2531.5,3673.23 2519.68,3685.04 2519.68,3704.72 2523.62,3708.66 v2(2523.62,3826.77)
  MidLayer3 w5: v1(2251.97,2956.69) 2212.6,2956.69 2181.1,2988.19 2181.1,3169.29 2248.03,3236.22 2326.77,3236.22 v1(2362.2,3271.65)
BUS_D14: U3.F6 U4.F22 U8.51 U12.37 | length 4204.6
  Top Layer w5: v2(1425.2,3850.39) U8.51@1425.2,3901.57 ; U4.F22@1858.27,1767.72 v1(1877.95,1787.4) ; v2(2413.38,3692.91) 2492.13,3771.65 v2(2492.13,3850.39) U12.37@2492.13,3901.57
  Top Layer w7.87: v1@2290.85,2957.19 U3.F6@2311.02,2977.36
  MidLayer1 w5: v2(1425.2,3850.39) 1425.2,3830.71 1519.69,3736.22 2334.65,3736.22 2377.95,3692.91 v2(2413.38,3692.91) ; v1(1877.95,1787.4) 1897.64,1767.72 2069.8,1767.72 2166.38,1864.3 2166.38,2029.61 2205.14,2068.37 2205.14,2205.14 2244.09,2244.09 2244.09,2263.78 2232.28,2275.59 2232.28,2610.24 2275.59,2653.54 2275.59,2673.23 2263.78,2685.04 2263.78,2696.85 2271.65,2704.72 2271.65,2937.01 v1(2291.34,2956.69) v1@2291.34,2957.68
  MidLayer2 w5: v1(2326.77,3271.65) 2385.83,3330.71 2385.83,3385.83 2377.95,3393.7 2377.95,3417.32 2405.51,3444.88 2433.07,3444.88 2456.69,3468.5 2480.31,3468.5 2503.94,3492.13 2503.94,3507.87 2511.81,3515.75 2511.81,3531.5 2492.13,3551.18 2488.19,3555.12 2488.19,3677.17 2496.06,3685.04 2496.06,3704.72 2492.13,3708.66 v2(2492.13,3850.39)
  MidLayer3 w5: v1(2291.34,2956.69) 2271.66,2937.01 2176.99,2937.01 2141.73,2972.27 2141.73,3145.67 2244.09,3248.03 2303.15,3248.03 v1(2326.77,3271.65)
BUS_D15: U3.G7 U4.D23 U8.53 U12.38 | length 3929.4
  Top Layer w5: v2(1362.2,3850.39) U8.53@1362.21,3901.57 ; U4.D23@1897.64,1846.46 v1(1917.32,1866.14) ; v1(2031,2215) 2059.05,2243.05 2059.05,2259.84 2047.24,2271.65 2047.24,2289.76 2231.1,2473.62 2231.1,2668.11 2251.97,2688.98 2251.97,2819.14 ; 2251.97,2814.96 v1(2251.97,2917.32) v1@2251.97,2918.31 ; v2(2381.89,3669.29) 2381.89,3696.85 2460.63,3775.59 v2(2460.63,3826.77) U12.38@2460.63,3901.57
  Top Layer w7.87: v1@2251.97,2918.31 U3.G7@2271.65,2937.99
  MidLayer1 w5: v2(1362.2,3850.39) 1362.2,3830.71 1468.5,3724.41 2326.77,3724.41 v2(2381.89,3669.29)
  MidLayer2 w5: v1(2291.34,3271.65) 2346.46,3326.77 2346.46,3385.83 2357.28,3396.65 2357.28,3416.34 2397.64,3456.69 2425.2,3456.69 2448.82,3480.32 2472.44,3480.32 2480.31,3488.19 2480.31,3507.87 2468.5,3519.69 2468.5,3673.23 2456.69,3685.04 2456.69,3704.72 2460.63,3708.66 v2(2460.63,3826.77)
  MidLayer3 w5: v1(1917.32,1866.14) 1917.32,1867.68 1936.9,1887.26 1936.9,1936.78 2048.69,2048.56 2048.69,2197.31 v1(2031,2215) ; v1(2251.97,2917.32) 2232.28,2897.64 2192.91,2897.64 2129.92,2960.63 2129.92,3149.61 2251.97,3271.65 v1(2291.34,3271.65)
BUS_D16: U4.F20 U9.2 U13.7 | length 3701
  Top Layer w5: U4.F20@1779.53,1767.72 v1(1799.21,1787.4)
  MidLayer3 w5: v1(1799.21,1787.4) 1818.9,1807.09 1818.9,2009.33 1943.4,2133.83 1943.4,2254.4 1967,2278 1967,2581.82 2051.18,2666 2051.18,2712.6 2086.61,2748.03 2488.19,2748.03 2791.34,3051.18 2791.34,3236.22 2791.34,3381.89 2838.58,3429.13 v2(2838.58,3500) ; v2(2051.18,3665.35) 2051.18,3578.74 2098.43,3531.5 2098.43,3519.68 2118.11,3500 v2(2118.11,3405.51)
  Bottom Layer w5: v2(2051.18,3665.35) 2086.61,3629.92 2763.78,3629.92 2826.77,3566.93 2826.77,3529.53 2838.58,3517.72 v2(2838.58,3500) 2818.9,3500 2807.09,3488.19 U13.7@2807.09,3452.76 ; v2(2118.11,3405.51) U9.2@2118.11,3452.76
BUS_D17: U4.D18 U9.4 U13.8 | length 3716.6
  Top Layer w5: U4.D18@1700.79,1846.46 1720.28,1865.94 v1@1720.47,1866.14
  MidLayer3 w5: v1@1720.47,1866.14 1740.55,1886.22 1773.62,1886.22 1779.53,1892.13 1779.53,2166.53 1846,2233 1859,2233 1897.81,2271.81 1897.81,2562.75 1996.06,2661 1996.06,2756.06 2011.65,2771.65 2480.31,2771.65 2767.72,3059.06 2767.72,3389.76 2807.09,3429.13 v2(2807.09,3523.62) ; v2(2019.68,3665.35) 2019.68,3590.55 2074.8,3535.43 2074.8,3519.68 2055.12,3500 v2(2055.12,3405.51)
  Bottom Layer w5: v2(2019.68,3665.35) 2066.93,3618.11 2696.85,3618.11 2751.97,3562.99 2751.97,3543.31 2771.65,3523.62 v2(2807.09,3523.62) 2807.09,3503.94 2775.59,3472.44 U13.8@2775.59,3452.76 ; v2(2055.12,3405.51) U9.4@2055.12,3452.76
  other v1: 1720.47,1865.75
BUS_D18: U4.B17 U9.5 U13.9 | length 3626.3
  Top Layer w5: U4.B17@1661.42,1925.2 v1@1681.1,1944.88
  MidLayer1 w5: v1@1679.92,1944.88 v1@1681.1,1946.06
  MidLayer3 w5: v1(1681.5,1945.28) 1681.5,1972.83 1725.2,2016.53 1725.2,2166.32 1803.15,2244.28 1803.15,2263.78 1789.37,2277.56 1789.37,2514.57 1917.32,2642.52 1917.32,2669.29 1933.07,2685.04 1933.07,2764.07 1964.28,2795.28 2472.44,2795.28 2744.09,3066.93 2744.09,3468.5 v2(2775.59,3500) ; v2(1988.19,3665.35) 1988.19,3566.93 2042.85,3512.27 ; v2(2023.62,3405.51) 2023.62,3476.38 2043.31,3496.06 2043.31,3512.27
  Bottom Layer w5: v2(1988.19,3665.35) 2047.24,3606.3 2688.98,3606.3 2732.28,3562.99 2732.28,3539.37 2724.41,3531.5 2724.41,3515.75 2740.16,3500 2744.09,3500 ; v2(2023.62,3405.51) U9.5@2023.62,3452.76 ; U13.9@2744.09,3452.76 2744.09,3500 ; v2(2775.59,3500) 2744.09,3500
BUS_D19: U4.F14 U9.7 U13.10 | length 3793
  Top Layer w5: U4.F14@1543.31,1767.72 1543.31,1767.32 v1(1563.39,1747.24)
  MidLayer3 w5: v1@1562.99,1747.24 v1(1563.39,1747.24) 1583.86,1767.72 1610.24,1767.72 1622.42,1779.9 1622.42,2138.17 1624.67,2140.42 1624.67,2230.82 1634.42,2240.57 1634.42,2260.25 1649.18,2275.01 1649.18,2436.98 1858.27,2646.06 1858.27,2673.23 1874.02,2688.98 1874.02,2761.02 1931.9,2818.9 2464.57,2818.9 2553.35,2907.68 ; v2(1956.69,3665.35) 1956.69,3535.43 1980.31,3511.81 1980.31,3496.06 1960.63,3476.38 v2(1960.63,3405.51) ; 2552.36,2908.66 2552.36,3040.58 2712.5,3200.72 2712.5,3213.15 ; 2712.51,3213.15 v2(2712.6,3500)
  Bottom Layer w5: v2(1956.69,3665.35) 2027.56,3594.49 2637.8,3594.49 2712.6,3519.69 v2(2712.6,3500) U13.10@2712.6,3452.76 ; v2(1960.63,3405.51) U9.7@1960.63,3452.76
BUS_D20: U4.B14 U9.8 U13.13 | length 3584.5
  Top Layer w5: U4.B14@1543.31,1925.2 v1(1562.99,1944.88)
  MidLayer3 w5: v1(1562.99,1944.88) 1543.31,1964.57 1543.31,2073.93 1614.17,2144.8 1614.17,2240.98 1615.73,2242.54 1615.73,2262.22 1602.94,2275.01 1602.94,2416.7 1673.95,2487.72 1737.28,2551.04 1743.33,2557.1 ; 1743.33,2557.11 1838.58,2652.36 1838.58,2669.29 1826.77,2681.1 1826.77,2696.85 1833.56,2703.64 1833.56,2756.43 1974.77,2897.64 2106.3,2897.64 2129.92,2874.02 2314.96,2874.02 2328.9,2887.95 2328.9,2943.07 2362.2,2976.38 2457.48,2976.38 2590.55,3109.45 2590.55,3370.08 2570.87,3389.76 2570.87,3421.26 2618.11,3468.5 v2(2618.11,3523.62) ; v2(1925.2,3665.35) 1925.2,3555.12 1909.45,3539.37 1909.45,3519.68 1929.13,3500 v2(1929.13,3377.95)
  Bottom Layer w5: v2(1925.2,3665.35) 2007.87,3582.68 2559.06,3582.68 v2(2618.11,3523.62) 2618.11,3500 U13.13@2618.11,3452.76 ; v2(1929.13,3377.95) U9.8@1929.13,3452.76
BUS_D21: U4.K11 U9.10 U13.14 | length 3754.1
  Top Layer w5: v1(1405.51,1629.92) U4.K11@1425.2,1610.24
  MidLayer3 w5: v1(1405.51,1629.92) 1425.2,1649.61 1425.2,2000.79 1478.25,2053.84 1478.25,2143.21 1550.87,2215.83 1550.87,2264.1 1539.96,2275.01 1539.96,2437.2 1751.97,2649.21 1751.97,2708.66 1992.13,2948.82 2078.74,2948.82 2118.11,2988.19 2118.11,3153.54 2145.67,3181.1 2263.78,3299.21 2523.62,3299.21 2566.93,3342.52 2566.93,3362.2 2547.24,3381.89 2547.24,3429.13 2586.61,3468.5 v2(2586.61,3500) ; v2(1866.14,3405.51) 1866.14,3500 1885.83,3519.68 1885.83,3535.43 1893.7,3543.31 v2(1893.7,3665.35)
  Bottom Layer w5: v2(1866.14,3405.51) U9.10@1866.14,3452.76 ; v2(1893.7,3665.35) 1988.19,3570.87 2535.43,3570.87 2586.61,3519.69 v2(2586.61,3500) U13.14@2586.61,3452.76
BUS_D22: U4.C10 U9.11 U13.15 | length 3422.6
  Top Layer w5: v1(1366.14,1905.51) U4.C10@1385.83,1885.83
  MidLayer3 w5: v1(1366.14,1905.51) 1366.14,2003.94 1429.13,2066.93 1429.13,2181.1 1521.26,2273.23 1521.26,2440.56 1740.16,2659.45 1740.16,2716.54 1984.25,2960.63 2070.87,2960.63 2106.3,2996.06 2106.3,3200.79 2216.54,3311.02 2496.06,3311.02 v1(2543.31,3358.27) ; v2(1834.65,3405.51) 1834.65,3476.38 1854.33,3496.06 1854.33,3511.81 1846.46,3519.69 1846.46,3566.93 1862.2,3582.68 v2(1862.2,3665.35)
  Bottom Layer w5: v2(1834.65,3405.51) U9.11@1834.65,3452.76 ; v2(1862.2,3665.35) 1968.5,3559.06 2507.87,3559.06 2535.43,3531.5 2535.43,3515.75 2555.12,3496.06 2555.12,3417.32 2555.12,3393.7 2543.31,3381.89 v1(2543.31,3358.27)
BUS_D23: U4.G9 U9.13 U13.16 | length 3654.5
  Top Layer w5: v1(1326.77,1748.03) U4.G9@1346.46,1728.35
  MidLayer3 w5: v1@1326.77,1747.64 v1@1326.97,1747.83 ; v1(1326.77,1748.03) 1346.46,1767.72 1346.46,1958.27 1346.46,2010.49 1368.13,2032.16 1368.13,2183.09 1374.02,2188.98 ; 1374.63,2189.59 1456.41,2271.37 1456.41,2410.74 1700.79,2655.12 1700.79,2700.79 1812.99,2812.99 1972.44,2972.44 2062.99,2972.44 2094.49,3003.94 2094.49,3204.72 2212.6,3322.83 2480.31,3322.83 2527.56,3370.08 ; v2(1771.65,3377.95) 1771.65,3429.13 1811.02,3468.5 1811.02,3507.87 1830.71,3527.56 v2(1830.71,3665.35) ; 2527.56,3369.83 v2(2527.56,3401.57)
  Bottom Layer w5: v2(1771.65,3377.95) U9.13@1771.65,3452.76 ; v2(1830.71,3665.35) 1948.82,3547.24 2496.06,3547.24 2511.81,3531.5 2511.81,3515.75 2503.94,3507.87 2503.94,3492.13 2523.62,3472.44 U13.16@2523.62,3452.76 2527.56,3448.82 v2(2527.56,3401.57)
BUS_D24: U4.B6 U9.42 U13.29 | length 3940.3
  Top Layer w5: v1@1208.66,1944.88 U4.B6@1228.35,1925.2
  MidLayer2 w5: v1@1208.66,1944.88 1209.46,1945.69 1228.35,1964.57 1228.35,2169.29 1339.64,2280.59 1339.64,2375.86 1404.33,2440.55 ; 1404.72,2440.16 1724.41,2759.84 2011.81,2759.84 2043.31,2791.34 2043.31,2968.5 2106.3,3031.5 2106.3,3236.22 2354.33,3484.25 2354.33,3507.87 2346.46,3515.75 2346.46,3696.85 2377.95,3728.35 2377.95,3834.65 2444.88,3901.57 2472.77,3901.57 v2(2523.62,3952.42) ; v2(1771.65,3948.82) 1771.65,3850.39 1830.71,3791.34 v2(1830.71,3704.72)
  Bottom Layer w5: U9.42@1771.65,3901.57 v2(1771.65,3948.82) ; v2(1830.71,3704.72) 1933.07,3807.09 2476.38,3807.09 2523.62,3854.33 U13.29@2523.62,3901.57 v2(2523.62,3952.42)
  other v1: 1208.79,1946.36
BUS_D25: U4.B7 U9.44 U13.30 | length 3929.3
  Top Layer w5: v1@1248.03,1944.88 U4.B7@1267.72,1925.2 1268.5,1924.41 U4.B7@1268.5,1924.02
  MidLayer2 w5: v2(1834.65,3948.82) 1834.65,3854.33 1862.2,3826.77 v2(1862.2,3704.72)
  MidLayer3 w5: v1@1248.03,1944.88 1247.37,1945.54 1227.97,1964.94 1227.97,2168.92 1288.98,2229.93 1338.58,2279.53 1338.58,2377.95 1647.64,2687.01 1647.64,2694.88 2003.94,3051.18 2031.5,3051.18 2070.87,3090.55 2070.87,3212.6 2204.72,3346.46 2440.94,3346.46 2472.44,3377.95 2472.44,3385.83 2484.25,3397.64 2484.25,3417.32 2490.16,3423.23 2543.31,3476.38 2543.31,3507.87 2535.43,3515.75 2535.43,3661.42 2562.99,3688.98 2562.99,3830.71 2574.8,3842.52 2574.8,3858.27 2555.12,3877.95 v2(2555.12,3952.76)
  Bottom Layer w5: U9.44@1834.65,3901.57 v2(1834.65,3948.82) ; v2(1862.2,3704.72) 1952.76,3795.28 2519.68,3795.28 2543.31,3818.9 2543.31,3834.65 2535.43,3842.52 2535.43,3862.2 U13.30@2555.12,3881.89 ; U13.30@2555.12,3901.57 v2(2555.12,3952.76)
  other v1: 1248.19,1946.36
BUS_D26: U4.A8 U9.45 U13.31 | length 3753.9
  Top Layer w5: v1@1287.99,1983.27 1306.69,1964.57 U4.A8@1307.09,1964.57
  MidLayer2 w5: v2(1866.14,3948.82) 1866.14,3877.95 1885.83,3858.27 1885.83,3842.52 1877.95,3834.65 1877.95,3818.9 1893.7,3803.15 v2(1893.7,3704.72)
  MidLayer3 w5: v1@1288.98,1984.25 1287.99,1985.24 1287.4,1985.83 1287.4,2162.99 1397.64,2273.23 ; 1398.03,2272.83 1398.03,2417.72 1659.45,2679.13 1964.57,2984.25 2051.18,2984.25 2082.68,3015.75 2082.68,3209.65 2089.57,3216.54 2207.68,3334.65 2476.38,3334.65 2511.81,3370.08 2511.81,3389.76 2507.87,3393.7 2507.87,3417.32 2566.93,3476.38 2566.93,3507.87 2574.8,3515.75 2574.8,3590.55 2590.55,3606.3 2590.55,3677.17 2582.68,3685.04 2582.68,3704.72 2586.61,3708.66 v2(2586.61,3826.77)
  Bottom Layer w5: U9.45@1866.14,3901.57 v2(1866.14,3948.82) ; v2(1893.7,3704.72) 1972.44,3783.46 2543.31,3783.46 v2(2586.61,3826.77) U13.31@2586.61,3901.57
  other v1: 1287.4,1984.65
BUS_D27: U4.C12 U9.47 U13.32 | length 4045
  Top Layer w5: v1(1444.88,1905.51) U4.C12@1464.57,1885.83
  MidLayer2 w5: v2(1925.2,3704.72) 1925.2,3818.9 1948.82,3842.52 1948.82,3858.27 1929.13,3877.95 v2(1929.13,3972.44)
  MidLayer3 w5: v1(1444.88,1905.51) 1464.57,1885.83 1491.09,1885.83 1513.96,1908.69 1513.96,2065.14 1601.99,2153.17 1601.99,2203.5 1569.27,2236.22 1569.27,2258.07 1588.18,2276.98 1588.18,2469.28 1763.78,2644.88 1763.78,2700.79 1972.44,2909.45 2114.17,2909.45 2139.61,2884.02 2310.82,2884.02 2318.9,2892.09 2318.9,2956.69 2377.95,3015.75 2456.69,3015.75 2468.5,3027.56 2468.5,3082.68 2480.31,3094.49 2523.62,3094.49 2578.74,3149.61 2578.74,3366.14 2559.06,3385.83 2559.06,3425.2 2606.3,3472.44 2606.3,3507.87 2598.43,3515.75 2598.43,3535.43 2614.17,3551.18 2614.17,3677.17 2622.05,3685.04 2622.05,3704.72 2618.11,3708.66 v2(2618.11,3850.39)
  Bottom Layer w5: v2(1925.2,3704.72) 1992.13,3771.65 2559.05,3771.65 2618.11,3830.71 v2(2618.11,3850.39) U13.32@2618.11,3901.57 ; U9.47@1929.13,3901.57 v2(1929.13,3972.44)
BUS_D28: U4.H15 U9.48 U13.35 | length 4450.6
  Top Layer w5: U4.H15@1582.68,1688.98 v1(1602.36,1708.66)
  MidLayer2 w5: v2(1956.69,3704.72) 1956.69,3795.28 1980.31,3818.9 1980.31,3834.65 1960.63,3854.33 v2(1960.63,3972.44)
  MidLayer3 w5: v1@1601.18,1708.66 1617.52,1725 1620.87,1728.35 1653.54,1728.35 1661.04,1735.85 1661.04,1996.44 1634.77,2022.71 1634.77,2204.5 1661.98,2231.71 1730.53,2231.71 1743.65,2244.83 1773.62,2274.8 1773.62,2525.98 1901.57,2653.94 1901.57,2669.29 1885.83,2685.04 1885.83,2751.83 1941.09,2807.09 2468.5,2807.09 2732.28,3070.87 2732.28,3507.87 2724.41,3515.75 2724.41,3531.49 2732.28,3539.37 2732.28,3559.06 2716.54,3574.8 2716.54,3677.17 2708.66,3685.04 2708.66,3704.72 2712.6,3708.66 2712.6,3799.21 2732.28,3818.9 2732.28,3834.65 2712.6,3854.33 v2(2712.6,3952.76)
  Bottom Layer w5: v2(1956.69,3704.72) 2011.81,3759.84 2618.11,3759.84 2712.6,3854.33 v2(2712.6,3952.76) ; U9.48@1960.63,3901.57 v2(1960.63,3972.44)
BUS_D29: U4.B18 U9.50 U13.36 | length 4135.5
  Top Layer w5: U4.B18@1700.79,1925.2 v1@1720.47,1944.88
  MidLayer2 w5: v2(1988.19,3704.72) 1988.19,3763.78 2043.31,3818.9 2043.31,3834.65 2023.62,3854.33 v2(2023.62,3948.82)
  MidLayer3 w5: v1(1720.87,1945.28) 1747.35,1971.76 1747.35,2156.35 1826,2235 1826,2263 1840,2277 1840,2533.43 1964.57,2658 1964.57,2669.29 1952.76,2681.1 1952.76,2755.76 1980.46,2783.46 2476.38,2783.46 2755.91,3062.99 2755.91,3393.7 2795.28,3433.07 2795.28,3507.87 2779.53,3523.62 2771.65,3523.62 2751.97,3543.31 2751.97,3559.06 2740.16,3570.87 2740.16,3677.17 2748.03,3685.04 2748.03,3704.72 2744.09,3708.66 2744.09,3822.83 2763.78,3842.52 2763.78,3858.27 2744.09,3877.95 v2(2744.09,3976.38)
  Bottom Layer w5: v2(1988.19,3704.72) 2031.5,3748.03 2661.42,3748.03 2732.28,3818.9 2732.28,3834.65 2724.41,3842.52 2724.41,3862.2 2744.09,3881.89 U13.36@2744.09,3901.57 v2(2744.09,3976.38) ; U9.50@2023.62,3901.57 v2(2023.62,3948.82)
BUS_D30: U4.A20 U9.51 U13.37 | length 3958.3
  Top Layer w5: U4.A20@1774.84,1960.6 1779.17,1964.93 v1@1794.53,1980.29
  MidLayer2 w5: v2(2019.68,3704.72) 2019.68,3767.72 2066.93,3814.96 2066.93,3834.65 2074.8,3842.52 2074.8,3858.27 2055.12,3877.95 v2(2055.12,3948.82)
  MidLayer3 w5: v1(1799.21,1984.25) 1799.21,2021.14 1899.12,2121.04 1899.12,2191.37 1933.05,2225.3 1933.05,2259.95 1918,2275 1918,2551.63 2039.37,2673 2039.37,2720.47 2078.74,2759.84 2484.25,2759.84 2778.54,3054.13 2778.54,3384.84 2818.9,3425.2 2818.9,3507.87 2826.77,3515.75 2826.77,3566.93 2779.53,3614.17 2779.53,3677.17 2771.65,3685.04 2771.65,3704.72 2775.59,3708.66 2775.59,3795.28 2795.28,3814.96 2795.28,3834.65 2775.59,3854.33 v2(2775.59,3952.76)
  Bottom Layer w5: v2(2019.68,3704.72) 2051.18,3736.22 2669.29,3736.22 2755.9,3822.83 2755.9,3834.65 2775.59,3854.33 U13.37@2775.59,3901.57 v2(2775.59,3952.76) ; U9.51@2055.12,3901.57 v2(2055.12,3948.82)
BUS_D31: U4.E21 U9.53 U13.38 | length 4150.5
  Top Layer w5: U4.E21@1818.9,1807.09 v1(1838.58,1826.77)
  MidLayer2 w5: v2(2051.18,3704.72) 2051.18,3755.91 2137.8,3842.52 2137.8,3862.2 2118.11,3881.89 v2(2118.11,3948.82)
  MidLayer3 w5: v1(1838.58,1826.77) 1858.27,1846.46 1858.27,2014.25 1985.71,2141.69 1985.71,2199.24 1993,2206.53 1993,2263 1981,2275 1981,2577.01 2062.99,2659 2062.99,2704.72 2094.49,2736.22 2492.12,2736.22 2803.15,3047.25 2803.15,3377.96 2858.27,3433.07 2858.27,3507.87 2850.39,3515.75 2850.39,3531.5 2866.14,3547.24 2866.14,3562.99 2803.15,3625.98 2803.15,3677.17 2811.02,3685.04 2811.02,3704.72 2807.09,3708.66 2807.09,3822.83 2826.77,3842.52 2826.77,3858.27 2807.09,3877.95 v2(2807.09,3952.76)
  Bottom Layer w5: v2(2051.18,3704.72) 2070.87,3724.41 2704.72,3724.41 2795.28,3814.96 2795.28,3834.65 2787.4,3842.52 2787.4,3862.2 2807.09,3881.89 U13.38@2807.09,3901.57 v2(2807.09,3952.76) ; U9.53@2118.11,3901.57 v2(2118.11,3948.82)
BUS_FLASH_NBUSY: U3.A4 U4.M23 | length 2221.9
  Top Layer w5: U4.M23@1897.64,1531.5 v1(1917.32,1551.18) ; U3.A4@2507.87,3056.1 2507.87,3055.91 2519.19,3044.58 ; 2519.12,3044.66 2519.19,3044.58 ; v1(2584.25,3037.01) 2526.77,3037.01 2519.19,3044.58
  MidLayer2 w5: v1(2578.35,2142.91) 2579.53,2144.09 2579.53,2282.68 2547.58,2314.63 2547.58,2823.17 2621.65,2897.24 2621.65,3000 2584.65,3037.01 v1(2584.25,3037.01)
  MidLayer4 w5: v1(1917.32,1551.18) 1917.32,1523.62 1948.82,1492.13 2000.79,1492.13 2061.81,1553.15 2195.67,1553.15 2322.14,1679.62 2429.4,1679.62 2474.71,1724.93 2474.71,2039.28 v1(2578.35,2142.91)
BUS_FLASH_NCS: U3.F2 U4.G17 | length 1931.2
  Top Layer w5: U4.G17@1661.42,1728.35 v1(1681.1,1748.03) ; 1825.2,2256.69 1825.2,2230.71 v1(1851.18,2204.73) ; 1825.59,2256.69 1825.59,2262.6 1840.94,2277.95 1840.94,2298.03 1859.45,2316.54 1887.01,2316.54 2062.99,2492.52 2062.99,2648.82 2055.12,2656.69 2055.12,2716.54 2114.17,2775.59 2114.17,2956.69 2129.92,2972.44 2129.92,3122.05 2212.6,3204.72 2271.65,3204.72 2291.34,3185.04 2291.34,3161.42 2299.21,3153.54 v1(2330.71,3153.54) ; U3.F2@2310.03,3134.85 U3.F2@2311.02,3134.84
  Top Layer w7.87: U3.F2@2311.02,3134.84 v1(2330.71,3153.54)
  MidLayer2 w5: v1(1681.1,1748.03) 1683.09,1748.03 1701.16,1766.11 1701.16,1961 1750.93,2010.77 1750.93,2104.47 v1(1851.18,2204.73)
BUS_FLASH_NRESET: U3.B5 U4.N24 | length 2590.5
  Top Layer w5: U4.N24@1937.01,1492.13 v1(1956.69,1511.81)
  Top Layer w7.87: v1(2448.82,3035.43) U3.B5@2468.5,3016.73
  MidLayer1 w5: v1(1956.69,1511.81) 2140.59,1511.81 2330.2,1701.42 2330.2,2058.55 2519.68,2248.03 2519.68,2263.78 2547.58,2291.67 2547.58,2832.94 2611.81,2897.17 2611.81,3005.12 2601.18,3015.75 2507.87,3015.75 2488.19,3035.43 v1(2448.82,3035.43)
  Bottom Layer w5: v1@2010,3150 2105,3055 2429.25,3055 v1(2448.82,3035.43) v1@2447.57,3035.43
  other v1: 2011.81,3149.61
BUS_NBE0: RN1.6 RN4.7 U4.J11 U8.15 U12.39 | length 4299.2
  Top Layer w5: v1(1405.51,1669.29) U4.J11@1425.2,1649.61 ; U8.15@1771.65,3452.75 v2(1771.65,3503.93) ; v2(2429.13,3850.39) U12.39@2429.13,3901.57
  MidLayer2 w5: v1(1405.51,1669.29) 1385.83,1688.98 1385.83,2005.51 1434.25,2053.94 1434.25,2250.79 1413.38,2271.65 1413.38,2370.08 1652.08,2608.77 1700.79,2657.48 1700.79,2700.79 1736.22,2736.22 2023.62,2736.22 2102.36,2814.96 2102.36,2988.19 2129.92,3015.75 2129.92,3228.35 2370.08,3468.5 2417.32,3468.5 2440.94,3492.13 2440.94,3507.87 2448.82,3515.75 2448.82,3531.5 2425.2,3555.12 2425.2,3677.17 2433.07,3685.04 2433.07,3704.72 2429.13,3708.66 v2(2429.13,3850.39) ; v1(1742.14,3311.02) 1742.14,3376 1771.65,3405.51 v2(1771.65,3503.93)
  MidLayer3 w5: v2(1771.65,3503.93) 1771.65,3657.49 1748.03,3681.1 1748.03,3767.72 1862.2,3881.89 2397.64,3881.89 v2(2429.13,3850.39)
  Bottom Layer w5: RN1.6@1688.58,3311.02 v1(1742.14,3311.02) RN4.7@1779.53,3311.02 RN4.7@1779.92,3311.02
BUS_NBE1: RN3.5 RN5.8 U4.D9 U8.39 U12.40 | length 3836.3
  Top Layer w5: v1(1326.77,1866.14) U4.D9@1346.46,1846.46 ; U8.39@1803.14,3901.57 v2(1803.14,3850.39) 1803.14,3818.9 1818.89,3803.15 2374.02,3803.15 v2(2397.64,3826.77) U12.40@2397.64,3901.57
  MidLayer2 w5: v1(1326.77,1866.14) 1326.77,1878.02 1307.09,1897.71 1307.09,2181.49 1367.46,2241.87 1367.46,2258.53 1351.57,2274.41 1351.57,2371.26 1635.83,2655.51 1728.35,2748.03 2015.75,2748.03 2090.55,2822.83 2090.55,2996.06 2118.11,3023.62 2118.11,3232.28 2366.14,3480.32 2409.45,3480.32 2417.32,3488.19 2417.32,3507.87 2405.51,3519.68 2405.51,3673.23 2393.7,3685.04 2393.7,3704.72 2397.64,3708.66 v2(2397.64,3826.77)
  MidLayer3 w5: v1@1617.92,4055.11 v1(1618.11,4055.11) 1653.55,4055.11 1708.66,4000 1708.66,3944.88 v2(1803.14,3850.39)
  Bottom Layer w5: RN3.5@1586.22,4055.11 v1(1618.11,4055.11) RN5.8@1676.19,4055.12 RN5.8@1677.17,4055.11
BUS_NBE2: RN1.5 RN4.8 U4.A18 U9.15 U13.39 | length 4975.7
  Top Layer w5: v1(1699.21,2046.85) 1700.79,2048.82 1700.79,2046.85 U4.A18@1700.79,1964.57
  MidLayer2 w5: v1(1699.21,2046.85) 1722,2069.64 1722,2112 1835,2225 1913.98,2225 1962.36,2273.38 1962.36,2655.27 1992.13,2685.04 1992.13,2696.85 2007.87,2712.6 2035.43,2712.6 2125.98,2803.15 2125.98,2976.38 2181.1,3031.5 2181.1,3177.17 2228.35,3224.41 2460.63,3224.41 2476.38,3208.66 2716.54,3208.66 2862.2,3354.33 2862.2,3374.02 2881.89,3393.7 2881.89,3507.87 2889.76,3515.75 2889.76,3531.5 2881.89,3539.37 2881.89,3732.28 2858.27,3755.91 2858.27,3834.65 2838.58,3854.33 v2(2838.58,3976.38) 2800,4014.96 2257.09,4014.96 2166.93,3924.8 2166.93,3683.46 2121.26,3637.8 1820.47,3637.8 1799.21,3659.06 v2(1799.21,3704.72)
  MidLayer3 w5: v2(1708.66,3377.95) 1708.66,3409.45 1791.34,3492.13 1791.34,3511.81 1783.46,3519.68 1783.46,3688.98 v2(1799.21,3704.72)
  Bottom Layer w5: U9.15@1708.66,3452.76 v2(1708.66,3377.95) 1708.66,3362.2 1688.98,3342.52 1688.98,3331.1 1688.58,3330.71 RN4.8@1779.53,3330.7 ; U13.39@2838.58,3901.57 v2(2838.58,3976.38)
BUS_NBE3: RN3.6 RN5.7 U4.J16 U9.39 U13.40 | length 5344.6
  Top Layer w5: U4.J16@1622.05,1649.61 v1(1641.73,1669.29)
  MidLayer1 w5: v2(1767.72,3704.72) 1787.4,3685.04 v2(2314.96,3685.04)
  MidLayer2 w5: v1(1641.73,1669.29) 1661.42,1688.98 1695.94,1688.98 1739.78,1732.82 1739.78,1795.73 1751.52,1807.46 1773.02,1807.46 1779.15,1813.59 1779.15,1959.14 ; v2(1677.17,3850.39) 1677.17,3795.28 v2(1767.72,3704.72) ; 1779.07,1959.14 1763.78,1974.44 1763.78,2085.78 1884,2206 1909.87,2206 1936.87,2233 1982,2233 1995,2246 1995,2261 1983,2273 1983,2629 2035.43,2681.43 2035.43,2692.91 2137.8,2795.28 2137.8,2968.5 2192.91,3023.62 2192.91,3173.23 2232.28,3212.6 2456.69,3212.6 2472.44,3196.85 2748.03,3196.85 2791.34,3240.16 2838.58,3240.16 2857.28,3221.46 2929.13,3221.46 2940.94,3233.27 2940.94,3277.56 2917.32,3301.18 2906.5,3301.18 2892.72,3314.96 2892.72,3324.8 2917.32,3349.41 2917.32,3377.95 2933.07,3393.7 2933.07,3511.81 2921.26,3523.62 2921.26,3574.8 2893.7,3602.36 2893.7,3750 2881.89,3761.81 2881.89,3834.65 2889.76,3842.52 2889.76,3866.14 2870.08,3885.83 v2(2870.08,3952.76)
  MidLayer3 w5: v1@1641.54,4035.43 1696.85,3980.12 1696.85,3870.08 v2(1677.17,3850.39)
  Bottom Layer w5: RN3.6@1586.22,4035.43 v1(1639.78,4035.43) RN5.7@1676.19,4035.43 RN5.7@1677.56,4035.43 ; v2(1677.17,3850.39) U9.39@1677.17,3901.57 ; v2(2314.96,3685.04) 2358.27,3641.73 2704.72,3641.73 2858.27,3795.28 2858.27,3834.65 2850.39,3842.52 2850.39,3862.2 2870.08,3881.89 U13.40@2870.08,3901.57 v2(2870.08,3952.76)
BUS_NOE: U3.G2 U4.A19 U12.41 U13.41 | length 3871.2
  Top Layer w5: U4.A19@1740.16,1964.57 1740.16,2064.16 1871.26,2195.26 1871.26,2258.66 1856.3,2273.62 1856.3,2288.19 1870.08,2301.97 1890.55,2301.97 1900.39,2311.81 ; 1899.45,2311.02 1975.33,2386.91 2077.56,2489.14 2077.56,2658.66 2066.93,2669.29 2066.93,2708.66 2125.98,2767.72 2125.98,2952.76 2141.73,2968.5 2141.73,3118.11 2216.54,3192.91 2240.16,3192.91 2251.97,3181.1 v1@2251.97,3154.53 ; v1@2255.91,3150.59 2255.91,3153.54 v1@2255.91,3154.53 ; v2(2366.14,3850.39) U12.41@2366.14,3901.57
  Top Layer w7.87: v1@2251.97,3154.53 2252.46,3154.04 2255.91,3150.59 U3.G2@2271.65,3134.84
  MidLayer3 w5: v2(2901.58,3952.76) 2901.57,3854.33 2940.94,3814.96 2940.94,3559.06 2925.2,3543.31 2925.2,3523.62 2933.07,3515.75 2933.07,3393.7 2917.32,3377.95 v1(2917.32,3321.85) v1@2917.32,3314.96
  MidLayer4 w5: v1(2251.97,3153.54) 2251.97,3263.78 2303.15,3314.96 2907.48,3314.96 v1(2917.32,3321.85) ; v2(2366.14,3850.39) 2366.14,3814.96 2374.02,3807.09 2909.45,3807.09 2921.26,3818.9 2921.26,3834.65 2901.58,3854.33 v2(2901.58,3952.76)
  Bottom Layer w5: U13.41@2901.57,3901.57 v2(2901.58,3952.76)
